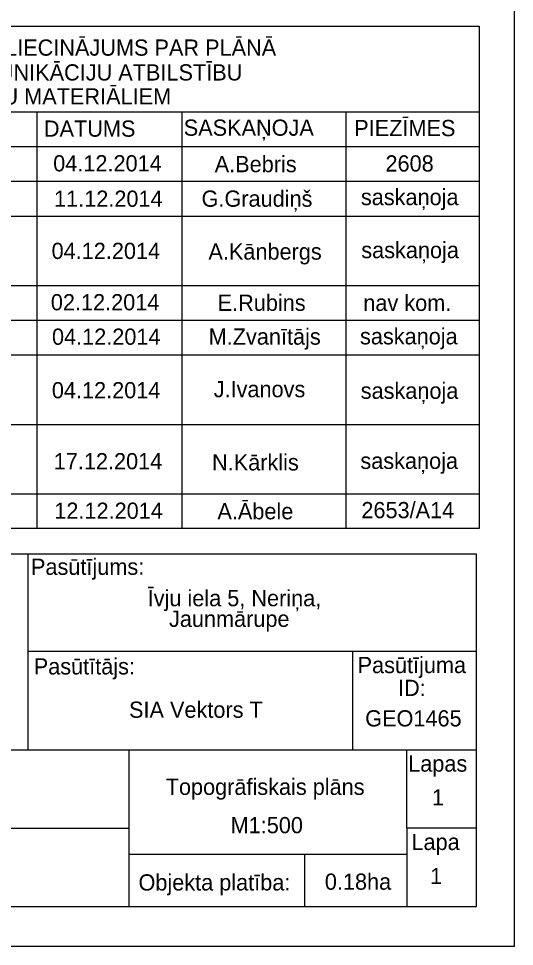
# Model space of a CAD drawing. Extents: x 496127 to 496334, y 303823 to 303967.
# Drawn here: x 496303.5 to 496334.1, y 303822.9 to 303880.1 of the extents above; entities that cross this region are included whole.
import ezdxf

# ---------------------------------------------------------------- set-up
doc = ezdxf.new("R2010")
doc.units = 0
doc.layers.add('RAMI_PLAN_####_TKST_#', color=7, linetype='Continuous')

msp = doc.modelspace()

# ---------------------------------------------------------------- linework, layer by layer
at = {"layer": 'RAMI_PLAN_####_TKST_#'}
for p, q in [((496334.105, 303822.887), (496334.105, 303966.843)), ((496270.361, 303879.638), (496331.919, 303879.638)), ((496331.919, 303879.638), (496331.919, 303848.658)), ((496331.919, 303874.337), (496270.361, 303874.337)), ((496304.636, 303874.337), (496304.636, 303848.658)), ((496313.587, 303874.337), (496313.587, 303848.658)), ((496323.695, 303874.337), (496323.695, 303848.658)), ((496331.919, 303872.195), (496270.361, 303872.195)), ((496331.919, 303870.052), (496270.361, 303870.052)), ((496331.919, 303867.91), (496270.361, 303867.91)), ((496331.919, 303863.626), (496270.361, 303863.626)), ((496331.919, 303861.484), (496270.361, 303861.484)), ((496331.919, 303859.344), (496270.361, 303859.344)), ((496331.919, 303855.064), (496270.361, 303855.064)), ((496331.919, 303850.784), (496270.361, 303850.784)), ((496331.919, 303848.658), (496270.361, 303848.658)), ((496270.42, 303847.11), (496331.742, 303847.109)), ((496304.095, 303847.109), (496304.095, 303835.002)), ((496331.742, 303847.109), (496331.742, 303825.336)), ((496304.095, 303841.092), (496331.742, 303841.092)), ((496324.112, 303841.092), (496324.112, 303835.002)), ((496270.42, 303835.002), (496331.742, 303835.002)), ((496310.321, 303835.002), (496310.321, 303825.336)), ((496327.457, 303835.002), (496327.458, 303825.336)), ((496310.321, 303830.166), (496270.42, 303830.165)), ((496327.458, 303830.205), (496331.742, 303830.205)), ((496310.32, 303828.582), (496327.458, 303828.582)), ((496321.153, 303828.581), (496321.153, 303825.335)), ((496331.742, 303825.336), (496270.42, 303825.335)), ((496334.105, 303822.887), (496138.105, 303822.887))]:
    msp.add_line(p, q, dxfattribs=at)

# ---------------------------------------------------------------- texts
for s, p in [(' EKSPLUATĒJOŠO ORGANIZĀCIJU APLIECINĀJUMS PAR PLĀNĀ', (496278.317, 303877.82)), (' UZRĀDĪTO APAKŠZEMJU KOMUNIKĀCIJU ATBILSTĪBU', (496282.327, 303876.29)), (' ŠO ORGANIZĀCIJU ARHĪVU MATERIĀLIEM', (496285.441, 303874.811)), ('DATUMS', (496305.082, 303872.824)), ('SASKAŅOJA', (496313.707, 303872.883)), ('PIEZĪMES', (496324.223, 303872.858)), ('A.Bebris', (496315.617, 303870.634)), ('2608', (496326.15, 303870.676)), ('11.12.2014', (496305.709, 303868.501)), ('G.Graudiņš', (496314.806, 303868.505)), ('saskaņoja', (496324.634, 303868.603)), ('saskaņoja', (496324.658, 303865.332)), ('04.12.2014', (496305.556, 303865.283)), ('A.Kānbergs', (496315.23, 303865.243)), ('02.12.2014', (496305.511, 303862.117)), ('E.Rubins', (496315.798, 303862.084)), ('nav kom.', (496324.784, 303862.079)), ('M.Zvanītājs', (496315.245, 303859.997)), ('saskaņoja', (496324.58, 303860.016)), ('J.Ivanovs', (496315.556, 303856.756)), ('04.12.2014', (496305.574, 303856.691)), ('saskaņoja', (496324.623, 303856.658)), ('17.12.2014', (496305.688, 303852.314)), ('N.Kārklis', (496315.453, 303852.243)), ('saskaņoja', (496324.603, 303852.335)), ('A.Ābele', (496315.783, 303849.227)), ('2653/A14', (496324.664, 303849.296))]:
    msp.add_text(s, height=1, dxfattribs=at).set_placement(p)
for s, rotation, p in [('04.12.2014', 359.9987, (496305.657, 303870.686)), ('04.12.2014', 359.9987, (496305.581, 303859.993)), ('12.12.2014', 359.9987, (496305.724, 303849.261)), ('Pasūtījums:', 0.024, (496304.286, 303845.802)), ('Īvju iela 5, Neriņa,', 0, (496311.485, 303843.867)), ('Jaunmārupe', 0, (496312.798, 303842.593)), ('Pasūtītājs:', 0.024, (496304.455, 303839.658)), ('Pasūtījuma', 0.024, (496324.431, 303839.741)), ('ID:', 0.024, (496326.925, 303838.333)), ('SIA Vektors T', 0, (496310.333, 303836.987)), ('GEO1465', 0, (496324.899, 303836.454)), ('Lapas', 0.024, (496327.551, 303833.664)), ('Topogrāfiskais plāns', 359.9996, (496312.595, 303832.233)), ('1', 0.024, (496329.017, 303831.581)), ('M1:500', 0, (496316.599, 303829.868)), ('Lapa', 0.024, (496327.753, 303828.831)), ('0.18ha', 0, (496322.411, 303826.383)), ('1', 0.024, (496328.904, 303826.729)), ('Objekta platība:', 0.024, (496310.917, 303826.335))]:
    msp.add_text(s, height=1, rotation=rotation, dxfattribs=at).set_placement(p)

doc.saveas('drawing.dxf')
